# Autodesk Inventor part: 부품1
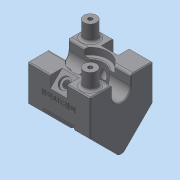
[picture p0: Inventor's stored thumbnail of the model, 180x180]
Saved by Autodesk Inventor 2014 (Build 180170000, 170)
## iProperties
Created: 2025-02
Part Number: 부품1
Material: 일반
Document SubType Name: Modeling
Designer: dg
Density: 1 g/cm^3
Appearance: 기본값
Author: dg
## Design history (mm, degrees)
sketch "스케치1"
  geometry: L1 (-37, 75.27)-(37, 75.27); L2 (37, 75.27)-(37, 33.27); L3 (37, 0)-(-37, 0); L4 (-37, 33.27)-(-37, 75.27); L5 (-37, 75.27)-(37, 0); L6 (37, 75.27)-(-37, 0); L7 (-37, 33.27)-(37, 33.27); L8 (-37, 33.27)-(0, -3.73); L9 (37, 33.27)-(0, -3.73); L10 (37, 33.27)-(37, 0); L11 (-37, 33.27)-(-37, 0); 4 further points
  constraints: 22 end point, 4 midpoint, 3 parallel, 3 perpendicular, 2 vertical alignment, 1 coincident, 1 horizontal
  dimensions: "d4" = 74 distance of L3.start L3.end; "d5" = 75.27 distance of L1.end L3.start; "d6" = 42 distance between parallel lines of L1 L7; "d8" = 45 deg angle of L7 L8; "d9" = 45 deg angle of L7 L9; "d10" = 90 deg angle of L9 L8 (derived)
extrude "돌출2" new body sketch "스케치1" distance "d11" = 74; taper "d12" = 0 deg
fillet "모깎기1" dims "d13" = 6
node "작업 평면1"
sketch "스케치3"
  geometry: L1 (75.27, 37)-(75.27, -37) reference; L2 (63.27, 11)-(75.27, 11); L3 (63.27, -11)-(75.27, -11); A1 r 11 centre (63.27, 0) between (63.27, 11) and (63.27, -11); 1 further point
  constraints: 4 end point, 2 perpendicular, 2 point on circle, 2 point on line, 2 tangent, 1 centre point
  dimensions: "d18" = 22 diameter of A1; "d19" = 12 distance from line of A1.centre L1
extrude "돌출4" cut sketch "스케치3" distance "d20" = 74; taper "d21" = 0 deg
sketch "스케치4"
  geometry: L1 (74, 26)-(74, 0) reference; L2 (37, 63.855)-(37, 15.792); L3 (0, 74)-(0, 48) reference; C1 r 21 at (37, 37); 1 further point
  constraints: 2 end point, 1 centre point, 1 horizontal alignment, 1 parallel, 1 point on line
  dimensions: "d22" = 37 distance between parallel lines of L2 L3; "d23" = 42 diameter of C1
extrude "돌출5" cut sketch "스케치4" distance "d24" = 8; taper "d25" = 0 deg
sketch "스케치6" dims "d30" = 70
  geometry: L1 (74, 0)-(74, -26) reference; L2 (37, -37)-(-8.293, 8.293); L3 (37, -37)-(101.054, -37); L4 (17, 4.27)-(17, -81.772); L5 (0, -32.757)-(0, 0) reference; L6 (0, -13)-(74, -13); C1 r 7.5 at (12.251, -12.251); A1 r 21 centre (37, -37) between (54.889, -26) and (19.111, -26) reference; 1 further point
  constraints: 8 end point, 2 point on line, 1 centre point, 1 coincident, 1 equal length, 1 horizontal, 1 midpoint, 1 perpendicular, 3 other
  dimensions: "d29" = 15 diameter of C1; "d31" = 135 deg angle of L3 L2; "d32" = 20 distance from line of A1.centre L4
extrude "돌출7" join sketch "스케치6" distance "d33" = 19; taper "d34" = 0 deg
hole "구멍1" diameter "d37" = 4.917; stored, may be unused: countersink angle "d41" = 90 deg, drill point angle "d43" = 118 deg; dims "d35" = 10, "d36" = 10, "d38" = 12, "d39" = 4, "d40" = 2, "d42" = 14
node "작업 평면2"
sketch "스케치7"
  geometry: C1 r 16 at (37, -37); A1 r 21 centre (37, -37) between (54.889, -26) and (19.111, -26) reference; 1 further point
  constraints: 1 centre point, 1 coincident
  dimensions: "d44" = 32 diameter of C1
extrude "돌출8" cut sketch "스케치7" distance "d45" = 28; taper "d46" = 0 deg
sketch "스케치8"
  geometry: L1 (-75.27, 37)-(-48.426, 10.156); L2 (-33.27, 37)-(-0.513, 4.243) reference; L3 (-75.27, 37)-(-75.27, 23); L4 (-75.27, 37)-(-75.27, 11) reference; L5 (-75.27, 37)-(-61.27, 37); L6 (-61.27, 37)-(-75.27, 23); 1 further point
  constraints: 8 end point, 1 parallel, 1 perpendicular, 1 point on line
  dimensions: "d47" = 14 distance of L1.start L3.end; "d48" = 14 distance of L1.start L5.end
extrude "돌출9" cut sketch "스케치8" stored distance "d49" = 20; taper "d50" = 0 deg
sketch "스케치9"
  geometry: 2 further points
hole "구멍2" sketch "스케치9" at (10, -9.899) diameter "d51" = 8; stored, may be unused: countersink angle "d55" = 90 deg, drill point angle "d57" = 118 deg; dims "d52" = 12, "d53" = 13, "d54" = 3, "d56" = 30.64403
sketch "스케치10"
  geometry: 1 further point
fillet "모깎기2" dims "d58" = 3
sketch "스케치11"
  geometry: L1 (74, 0)-(0, 0) reference; L2 (55, 3)-(19, 3); L3 (19, 3)-(19, -61.151); L4 (19, -61.151)-(55, -61.151); L5 (55, -61.151)-(55, 3); L6 (55, 3)-(19, -61.151); L7 (19, 3)-(55, -61.151); 2 further points
  constraints: 12 end point, 2 midpoint, 2 parallel, 1 horizontal, 1 perpendicular
  dimensions: "d60" = 36 distance of L4.end L3.end; "d61" = 3 distance between parallel lines of L1 L2
extrude "돌출10" cut sketch "스케치11" distance "d62" = 3; taper "d63" = 0 deg
chamfer "모따기1" distance "d64" = 1; stored, may be unused: second distance "d65" = 2, angle "d66" = 45 deg
chamfer "모따기2" distance "d67" = 1; stored, may be unused: second distance "d68" = 2, angle "d69" = 45 deg
fillet "모깎기3" dims "d70" = 3
sketch "스케치12"
  geometry: L1 (27.249, 33)-(42.249, 33) reference; 3 further points
  constraints: 1 coincident, 1 other
  dimensions: "d71" = 40 distance from line of L1 point (10, -7)
feature "엠보싱1" sketch "스케치12" dims "d4" = 74, "d5" = 75.27, "d6" = 42, "d8" = 45 deg, "d9" = 45 deg, "d10" = 90 deg (derived), "d72" = 0.5, "d73" = 0
node "솔리드2"
mirror "대칭1"
mirror "대칭2"
mirror "대칭3"
